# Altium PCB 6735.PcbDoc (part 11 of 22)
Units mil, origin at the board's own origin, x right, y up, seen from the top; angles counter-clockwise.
Board outline 2641.73 x 5165.35 mil, 6 copper layers (Top, Inner Layer 2, Inner Layer 3, Inner Layer 4, Inner Layer 5, Bottom), stack 35.7 mil thick; 1011 components, 790 nets, 4118 pads, 9325 vias.
Unrouted connection lines stored in the file: 4610.
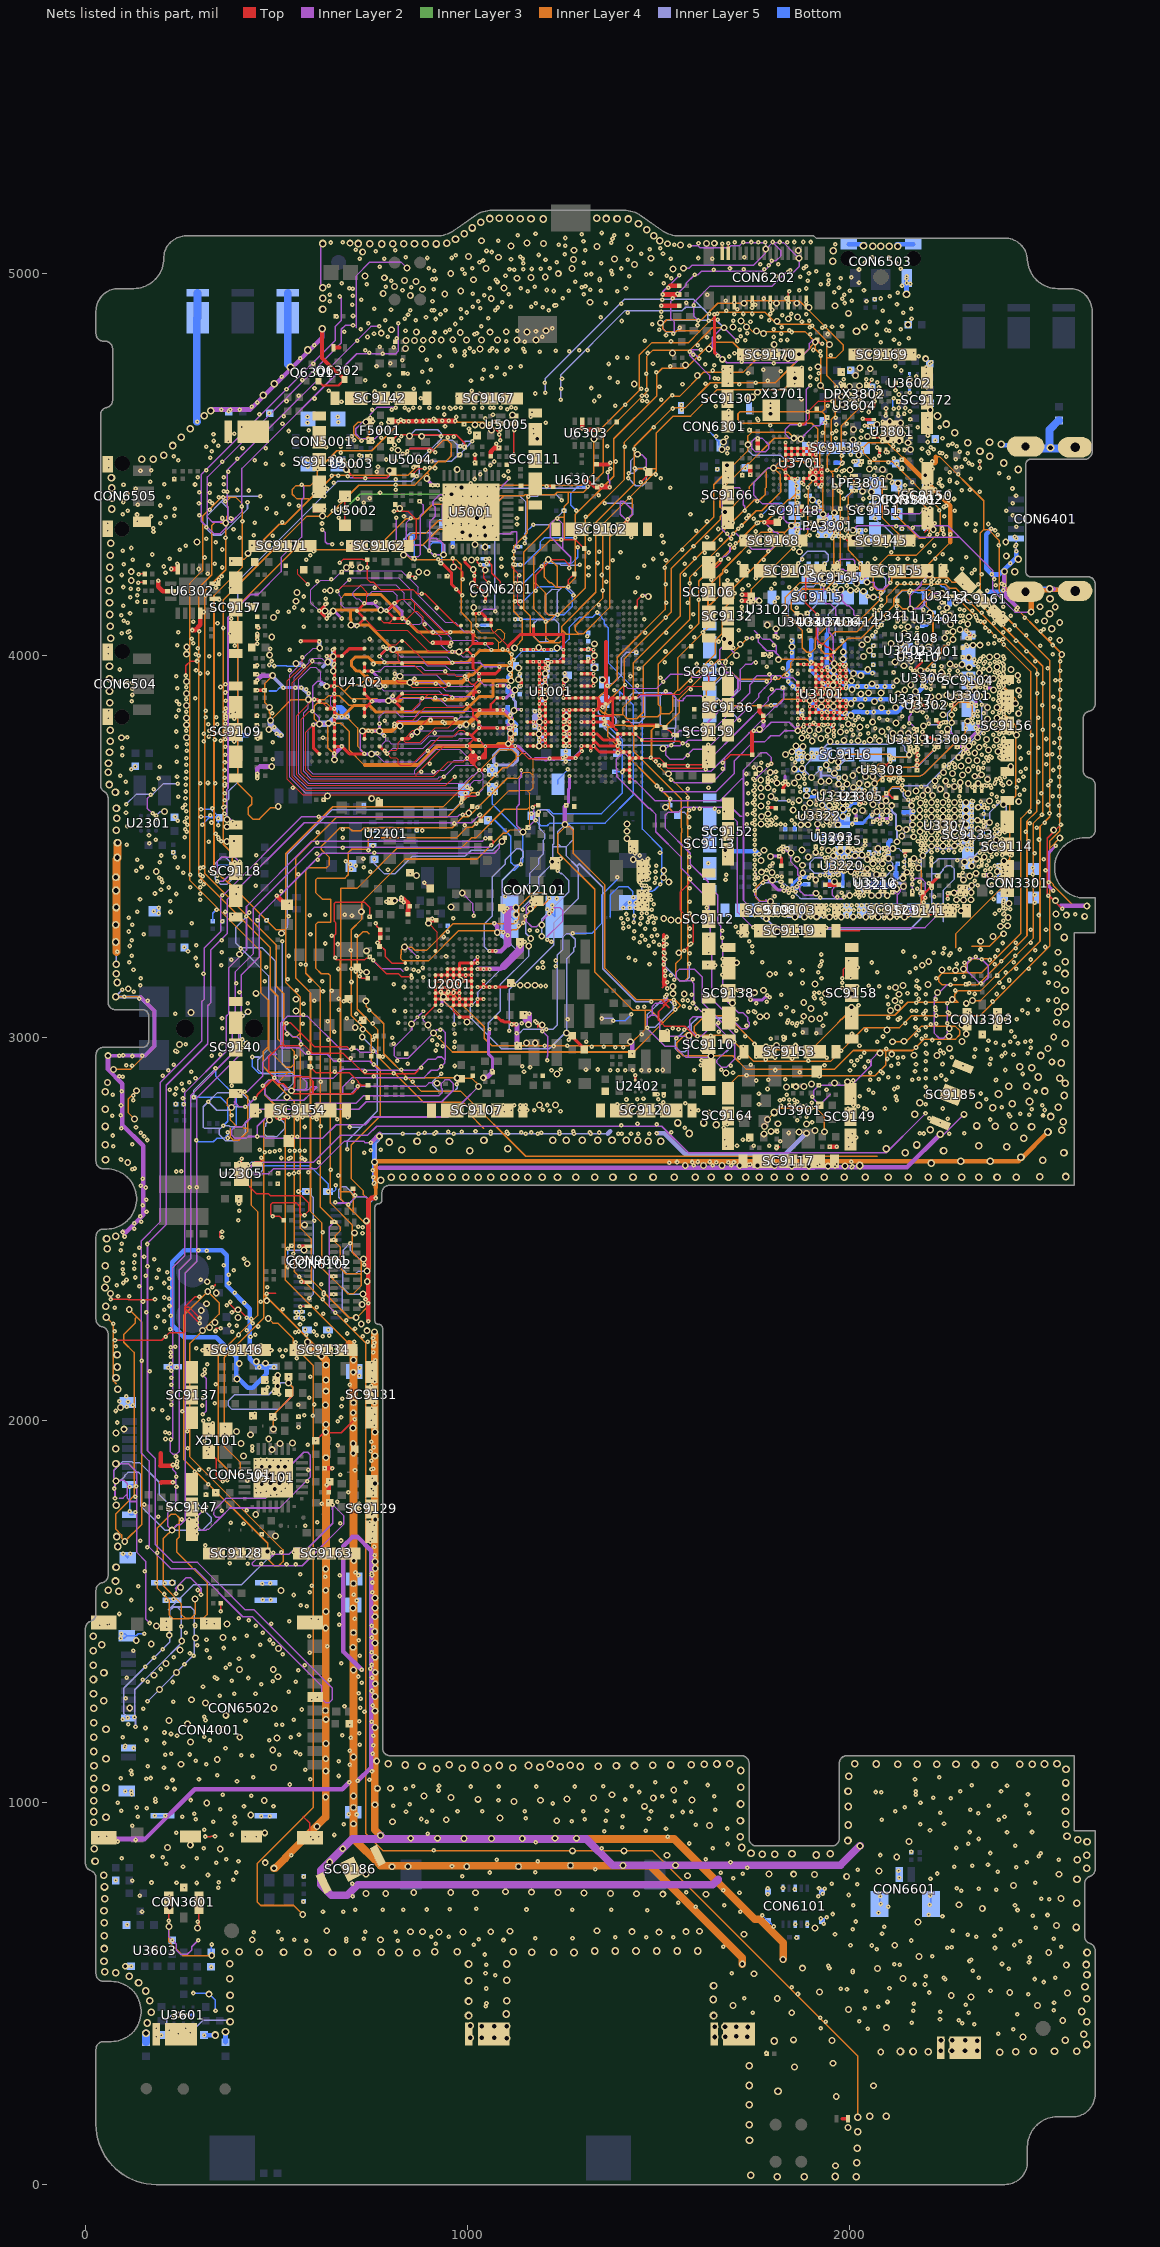
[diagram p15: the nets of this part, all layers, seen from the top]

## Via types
v1: diameter 12, hole 4, Top to Inner Layer 2, 3329 vias
v2: diameter 12, hole 4, Inner Layer 5 to Bottom, 3071 vias
v3: diameter 18, hole 10, Inner Layer 2 to Inner Layer 5, 1928 vias
v4: diameter 10, hole 4, Top to Inner Layer 2, 525 vias
v5: diameter 20, hole 12, Top to Bottom, 472 vias

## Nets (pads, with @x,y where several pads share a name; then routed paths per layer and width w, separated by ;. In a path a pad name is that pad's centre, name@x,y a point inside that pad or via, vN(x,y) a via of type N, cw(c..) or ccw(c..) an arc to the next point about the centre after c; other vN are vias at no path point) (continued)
D_GND: (continued)
  Bottom w8: U3601.6@231.43,443.38 256.33,443.38 U3601.9@256.43,443.38 260.91,443.38 U3601.2@281.43,443.38 ; v2(517.83,3916.61) v2(549.33,3916.61) v2(565.07,3916.61) ; C3248.2@1830.65,3545.59 v2(1830.65,3557.59) ; v2(1849.53,3391.68) 1849.53,3391.79 1848.24,3393.08 1848.24,3400.38 1868.13,3420.28 1880.65,3420.28 U3203.2@1886.76,3420.28 ; C3249.2@1855.65,3545.59 v2(1855.65,3559.59) ; v2@1858.65,3381.59 1858.65,3382.07 v2(1857.78,3382.95) 1856.03,3384.69 1864.29,3392.95 1872.88,3401.54 ; 1872.91,3401.57 U3203.1@1886.76,3401.57 ; U3203.14@1886.76,3630.9 1912.84,3630.9 1977.8,3565.94 U3203.50@1980.75,3565.94 ; U3203.40@1946.99,3401.57 1946.99,3454.43 1977.8,3485.24 U3203.49@1980.75,3485.24 ; v2(1974.87,3436.76) 1981.94,3429.69 1981.94,3415.72 1981.64,3415.42 U3203.38@1981.64,3401.57 ; v2(1981.65,3652.59) U3203.20@1981.64,3649.61 1981.64,3611.66 1980.75,3610.78 1980.75,3586.68 ; v2@1986.48,3436.4 1981.64,3439.52 1980.75,3440.4 1980.75,3473.59 U3203.49@1980.75,3483.15 ; U3203.34@2024.55,3437.6 2003.61,3437.6 1981.62,3459.59 1981.62,3483.15 U3203.49@1980.75,3483.15 ; U3203.31@2024.55,3489.57 2009.65,3489.57 1980.75,3489.57 U3203.49@1980.75,3485.24 ; U3203.24@2024.55,3613.58 2007.66,3613.58 1980.75,3586.68 ; C3243.2@2051.34,3580.59 2043.65,3572.9 2043.65,3572.55 2038.65,3567.55 2038.65,3566.59 2033.68,3561.61 U3203.27@2024.55,3561.61 1980.75,3561.61 U3203.50@1980.75,3565.94 ; L3234.2@2120.65,3430.59 2120.65,3450.59 C3289.2@2125.65,3455.59 ; U3602.6@2156.3,4688.09 v2@2156.3,4702.09 ; v2(2156.3,4704.09) U3602.9@2156.3,4713.09 2156.3,4725.09 ; L3415.2@2189.15,4078.59 2200.52,4078.59 v2(2208.16,4086.23) ; U3203.49@1980.75,3483.15 U3203.49@1980.75,3485.24 ; U3203.50@1980.75,3565.94 1980.75,3586.68
  Bottom w10: NTC6302.2@1860.65,3700.59 1871.65,3700.59 1881.15,3691.09 v2(1880.65,3690.59) ; L3414.1@1979.15,4038.59 1985.84,4031.91 v2(1985.84,3972.92) ; 2002.25,3956.09 v2@2061.65,3956.09 ; v2(2027.65,3380.59) 2027.3,3380.94 2046.95,3400.59 U3216.2@2070.65,3400.59 ; v2(2258.65,4149.88) 2260.25,4149.88 2260.25,4135.24 L3442.1@2260.57,4135.24
  Bottom w12: v2(310.3,391.09) v5(339.3,391.09) ; R3601.2@366.3,372.09 v5(366.3,400.09) ; v2(388.44,3791.68) 424.31,3791.68 ; v2(500.12,3796.33) 505.88,3796.33 505.88,3792.2 v2(511.65,3792.2) ; v2(655.06,3840) 655.06,3865.49 662.04,3865.49 ; v2(670.06,3840) 670.06,3857.47 662.04,3865.49 ; v2(685.06,3840) 685.06,3849.24 668.81,3865.49 662.04,3865.49 ; v2(698.52,786.81) v2@698.52,787.09 ; v2(755.68,2621.09) 755.68,2730.96 770.81,2746.09 ; C2402.2@756.31,3466.57 C2402.2@756.31,3467.09 ; v2(961.08,4285.11) 961.45,4284.74 C5013.2@961.45,4307.99 ; C10077.2@1104.95,3827.49 1118.95,3827.49 1127.45,3818.99 v2(1123.95,3815.49) ; C10072.2@1104.95,3865.49 1104.95,3851.78 v2(1111.93,3844.8) ; C10076.2@1105.95,3935.49 1105.95,3944.99 v2(1110.95,3949.99) ; v2(1107.95,3919.49) 1104.95,3916.49 C10073.2@1104.95,3905.49 1114.95,3895.49 v2(1117.95,3895.49) ; 1113.95,3765.49 1113.95,3777.49 1116.95,3780.49 1115.95,3781.49 v2(1115.7,3781.26) ; 1676.27,3488.59 1754.29,3488.59 v2(1762.23,3480.65) ; L3421.2@1849.15,4038.59 1849.15,3990.84 1838.65,3980.34 v2(1838.65,3932.59) v2(1850.65,3920.59) 1851.84,3921.78 1860.95,3912.67 v2(1862.13,3913.86) 1863.69,3915.41 1874.29,3904.8 1874.29,3904.32 1925.23,3853.38 1967.43,3853.38 1972.22,3848.59 v2(1986.65,3848.59) 2006.17,3848.59 2010.5,3852.92 2029.8,3852.92 2031.14,3851.59 v2(2045.65,3851.59) 2045.65,3852.13 2062.75,3852.13 v2(2062.75,3852.67) 2081.59,3852.67 2081.84,3852.42 v2(2100.84,3852.42) 2122.34,3852.42 v2(2140.34,3870.42) 2141.12,3869.64 2153.36,3881.88 v2(2154.15,3881.09) 2189.34,3916.27 v2(2189.34,3920.42) 2189.34,3923.77 2219.15,3953.59 ; L3411.1@1899.15,4038.59 1899.15,3961.92 1943.93,3917.14 v2(1974.68,3886.39) v2(2013.18,3886.39) v2(2039.68,3886.39) v2(2080.18,3886.39) v2(2108.18,3886.39) ; v2@1914.31,4402.09 v2(1919.31,4402.09) ; 1939.27,4056.21 1939.27,4053.35 1939.15,4053.24 1939.15,3971.11 v2(1940.34,3969.92) v2(1990.84,3919.42) v2(2019.84,3919.42) v2(2043.34,3919.42) v2(2071.34,3919.42) v2(2091.84,3919.42) v2@2112.56,3919.42 ; L3822.2@1963.31,4505.09 v2(1981.31,4505.09) ; v5(2035.58,5072.42) 2035.27,5076.21 v5@2038.7,5076.49 ; U3216.2@2070.65,3400.59 L3223.2@2115.65,3400.59 ; L3214.2@2100.65,3480.59 v2(2100.65,3485.59) 2100.65,3510.59 C3245.2@2105.65,3515.59 ; v2(2120.64,3405.02) 2120.36,3405.3 L3223.2@2115.65,3400.59 ; L3234.2@2120.65,3430.59 2120.65,3418.59 2115.65,3413.59 L3223.2@2115.65,3400.59 ; v5(2124.97,5071.19) 2123.08,5076.11 v5@2122.46,5076.49 ; C3255.2@2140.65,3590.59 2165.65,3590.59 v2(2165.65,3592.59) ; v5(2148.08,4946.11) v5@2148.23,4946.26 ; v2(2359.84,4169.49) 2361.81,4167.53 CON6401.7@2459.56,4167.53 2459.56,4175.08 v5(2523.05,4175.08) 2523.05,4172.29 2589.48,4172.29 CON6401.8@2589.48,4169.5 ; v2(2370.31,4332.09) 2356.3,4318.07 2356.3,4227.73 2371.54,4212.49 2391.06,4212.49 2435.31,4256.75 v2(2435.31,4273.09) ; v5(2396.3,4553.09) 2396.3,4550.27 2459.56,4550.27 CON6401.6@2459.56,4547.45 ; CON6501.16@451.32,2139.17 430.31,2160.18 430.31,2291.11 369.31,2352.11 369.31,2431.26 356.49,2444.09 258.29,2444.09 226.77,2412.57 226.77,2248.41 258.09,2217.09 342.31,2217.09 394.31,2165.09 394.31,2115.49 424.72,2085.09 437.18,2085.09 473.57,2121.48 CON6501.16@473.57,2139.18 ; CON6501.16@451.32,2139.17 454.31,2139.17 CON6501.16@455.39,2139.17 ; CON6501.16@451.32,2139.17 CON6501.16@455.39,2139.17 ; CON6501.16@455.39,2139.17 CON6501.16@473.57,2139.18 ; CON6501.16@455.39,2139.17 CON6501.16@473.57,2139.18 ; v5@2038.7,5076.49 2035.58,5076.49 CON6503.5@1996.66,5076.49 v5@2038.7,5076.49 ; v5@2122.46,5076.49 2124.97,5076.49 CON6503.4@2165.95,5076.49 v5@2122.46,5076.49 ; v5@2148.23,4946.26 2148.23,4975.09 CON6503.1@2148.23,4987.91 v5@2148.23,4946.26
  Bottom w20: L3603.2@158.3,372.09 v5(158.3,396.09) ; v2(292.3,4612.09) 292.08,4611.86 291.31,4612.63 291.31,4884.13 ANT5002.2@293.31,4884.13 ANT5002.1@293.31,4949.09 ; ANT5001.1@529.31,4949.09 ANT5001.2@529.31,4884.13 529.31,4762.09 v5(536.53,4754.87) ; R3622.2@2546.95,4615.49 2522.3,4590.84 v5@2522.3,4542.09 ; CON6401.9@2589.48,4545.48 2589.48,4542.09 v5@2522.3,4542.09 ; CON6401.6@2459.56,4547.45 2459.56,4542.09 v5@2522.3,4542.09 ; CON6401.6@2459.56,4547.45 2459.56,4553.27 CON6401.6@2459.56,4547.45
  other v1: 2387.65,394.26 2427.57,406.04 2325.38,419.04 2294.15,422.15 2161.63,423.05 1936.69,425.91 2024.72,426.72 2438.1,445.42 1745.4,449.11 2310.76,449.54 2236.6,451.65 2533.27,456.18 2073.88,465.13 1047.3,466.82 2167,473.15 2534.12,475.88 1723.47,487.07 2367.87,506.5 1992.39,510.8 1048.99,512.38 2103.66,513.97 1847.48,516.6 2169.69,523.34 2196.53,523.35 2483.98,537.66 2245.8,541.24 2537.81,540.97 1072.61,547.81 1691.41,552.87 2007.56,555.83 2321.91,559.15 1943.15,572.58 1048.15,574.81 2115.96,576.17 2398.02,577.06 2317.59,588.31 2470.55,594.07 2215.35,596.76 2266.39,620.94 1668.63,622.05 2057.76,625.41 2429.79,626.69 2161.09,638.5 546.4,640.48 1093.7,639.77 1028.74,641.45 682.78,643.06 2533.66,642.76 1176.38,643.99 1274.24,644.83 1385.59,646.52 1467.43,646.52 1537.45,647.36 904.94,648.2 950.4,648.2 2378.32,651.38 2308.73,653.27 1961.05,654.96 504.37,661.07 731.68,661.93 811.45,661.93 2007.56,668.03 2485.77,671.98 2090.23,673.93 2242.22,702.42 2517.11,705.11 1955.68,707.79 147.98,714.25 2438.65,718.22 2100.74,726.6 2500.99,747.19 141.97,755.42 2291.01,768.42 2382.55,771.37 346.98,776.87 1952.1,787.48 2484.87,789.28 122.25,794.88 2210.88,800.02 320.54,809.85 1719.31,813.15 395.01,816.32 2435.63,830.46 2272.66,831.36 255.2,831.76 2361.31,836.73 211.45,839.48 341.83,842.05 400.32,846.11 94.51,853.97 175.5,859.41 2494.19,858.8 2432.74,886.53 2309.31,892.04 2337.07,904.14 313.95,910.49 651.05,914.62 237.56,920 2209.6,927.35 675.77,942.2 391.26,945.84 892.56,949.6 1361.01,951.68 2389.43,954.48 288.65,956.14 252.96,962.23 137.12,962.76 1535.5,963.35 1406.09,963.88 2469.26,970.97 838.62,974.93 1585.04,974.93 1037.66,976.25 973.49,976.78 1149.01,976.78 1302.36,976.78 1479.72,976.78 907.36,977.73 2314.63,981.01 352.98,981.87 160.69,984.52 2143.38,986.92 414.74,989.59 491.94,989.59 805.2,991.06 1222.73,996.98 84.32,999.12 2184.72,998.73 1080.59,1005.86 1412.46,1007.37 183.05,1008.69 1509.51,1015.85 121.29,1020.62 2465.94,1020.93 1448.52,1026.99 2067.24,1026.97 2171.95,1028.98 2288.74,1028.98 2395.47,1028.98 923.65,1031.03 837.78,1035.48 213.27,1038.3 743.1,1058.69 170.3,1063.61 121.34,1073.02 749.61,1081.27 162.56,1094.18 691.95,1098.49 288.09,1108.31 407.65,1123.15 506.8,1124.26 751.9,1126.8 224.95,1127.6 550.25,1130.95 691.95,1135.49 366.43,1140.97 104.63,1147.66 717.69,1150.43 752.86,1149.76 160.33,1162.14 325.21,1162.14 481.18,1162.14 693.95,1169.49 536.88,1169.94 752.85,1174.67 223.83,1178.85 716.83,1180.88 156.99,1194.45 499,1203.36 112.43,1204.47 749.42,1210.98 716.54,1211.91 418.79,1213.38 314.07,1214.5 544.68,1215.61 151.42,1244.58 718.98,1247.53 751.33,1253.45 229.4,1263.52 719.95,1270.49 105.75,1272.43 715.25,1285.44 749.6,1291.26 459.78,1309.03 722.95,1312.49 228.29,1314.76 490.34,1316.63 383.07,1318.19 150.31,1320.33 425.82,1325.18 107.97,1325.9 749.6,1326.25 338.76,1327.52 714.1,1329.11 556.98,1345.55 367.52,1352.39 749.13,1359.81 401.72,1375.71 325.54,1378.04 438.26,1381.93 717.1,1383.44 516.69,1387.39 273.46,1389.7 749.13,1392.43 124.68,1396.09 361.3,1403.69 292.12,1411.47 491.81,1414.45 714.63,1424.06 481.76,1424.78 389.28,1428.57 748.66,1431.19 262.58,1443.34 463.48,1443.47 445.2,1462.17 286.68,1464.33 663.84,1464.42 211.45,1473.99 427.46,1476.49 704.97,1480.53 664.48,1491.5 171.45,1505.83 578.73,1512.77 665.13,1539.85 545.21,1542.43 701.5,1543.44 587.07,1549.38 750.13,1550.16 592.03,1566.72 750.53,1575.24 627.2,1590 665.13,1594.66 749.54,1599.34 706.45,1602.39 155.12,1604.81 526.04,1622.69 549.72,1622.88 424.15,1623.7 460.02,1624.42 377.99,1625.61 441.76,1644.22 653.61,1644.46 394.59,1647.53 675.48,1646.89 756.44,1646.66 430.68,1650.2 381.28,1650.8 408.82,1650.8 695.89,1652.48 452.11,1654.04 512.33,1653.84 545.14,1653.84 564.14,1658.59 755.08,1668.27 745.46,1682.37 291.35,1702.37 752.04,1707.34 290.76,1718.53 755.08,1725.02 743.76,1732.42 291.06,1732.91 251.44,1740.04 291.28,1747.59 749.09,1753.07 236.51,1766.89 291.78,1767.74 291.35,1781.5 747.62,1783.3 752.4,1803.35 458.8,1809.55 446.26,1809.75 472.49,1813.41 748.35,1820.18 75.66,1820.99 445.85,1822.08 238.1,1826.01 445.53,1836.92 749.83,1848.2 237.34,1851.77 445.22,1851.75 445.17,1866.92 297.9,1869.63 747.79,1871.1 239.73,1876.18 239.62,1892.16 510.62,1894.35 530.99,1893.83 747.79,1893.63 491.79,1895 459.03,1895.9 474.51,1895.64 236.84,1904.89 746.86,1918.26 748.05,1943.14 223.06,1949.29 209.43,1950.62 219.44,1966.07 83.34,1993.67 308.05,1997.81 748.22,1999.43 322.41,2002.64 215.98,2005.61 668.67,2007.86 572.8,2013.26 443.09,2017.15 78.85,2023.96 749.41,2031.17 107.61,2035.25 669.92,2036.04 306,2038.17 224.57,2040.13 598.47,2040.98 88.2,2049.02 224.61,2054.57 306.92,2057.68 749.01,2060.54 107.26,2062.37 688.57,2062.98 224.6,2073.63 469.31,2075.09 476.53,2086.06 748.22,2090.31 224.59,2092.69 691.05,2092.82 224.25,2110.84 223.92,2128.99 749.81,2128.8 312.58,2132.46 318.96,2145.8 223.58,2147.14 749.41,2150.23 223.25,2165.29 410.62,2174.09 364.73,2175.61 388.23,2175.61 223.1,2178.07 677.66,2178.18 752.56,2178.07 456.19,2181.52 483.77,2181.52 601.65,2181.54 662.1,2181.58 523.97,2182.55 306.29,2182.95 376.58,2183.49 401.62,2183.13 508.52,2183.57 543.44,2182.77 562.31,2183.56 582.73,2182.77 620.43,2183.17 642.68,2182.89 222.61,2191.16 79.39,2192.88 753.66,2193.98 738.59,2205.21 752.37,2214.28 725.59,2218.96 621.34,2219.79 637.37,2221.37 400.43,2222.42 443.79,2223.06 578.12,2223.8 384.53,2231.53 76.39,2232.38 557.66,2231.92 597.73,2231.92 422.28,2235.29 221.57,2237.42 705.31,2239.5 396.13,2247.1 375.99,2248.78 561.37,2250.45 602.79,2251.32 72.31,2252.09 437.88,2253.85 682.17,2261.6 569.47,2264.39 223.48,2272.57 556.74,2276.37 219.79,2298.68 621.34,2316.02 732.74,2315.76 219.25,2317.15 623.12,2333.84 219.05,2346.41 475.31,2348.09 617.06,2355.94 98.37,2358.81 301.35,2367.07 219.59,2369.61 559.54,2375.45 375,2380 98.66,2382.57 387.5,2392.5 729.77,2406.15 555.91,2408.2 97.21,2411.26 414.88,2421.83 543.82,2435.41 91.99,2444.01 94.6,2461.1 724.81,2488.8 725.64,2505.13 127.55,2515.44 399.73,2523.32 143.1,2533.66 402.56,2547.66 150.02,2562.51 401.7,2566.21 144.36,2613.18 754.25,2618.81 753.28,2635.92 532.64,2643.24 545.62,2645.83 558.33,2648.95 582.5,2648.95 751.67,2653.34 129.05,2658.42 2004.64,2661.93 1738.86,2668.83 1784.08,2669.13 1870.63,2669.08 1820.01,2670.33 1920.71,2669.92 1965.94,2670.14 1527.76,2673.46 1696.75,2674.54 1547.8,2675.24 1587.47,2675.24 1602.34,2675.44 1633.88,2675.44 1650.54,2675.04 1682.2,2674.64 2003.3,2675.55 93.17,2681.05 511.89,2685.91 565.92,2685.91 536.95,2686.69 729.81,2699.15 469.31,2701.09 482.31,2702.09 495.31,2703.09 534.31,2705.09 547.31,2705.09 560.31,2705.09 573.31,2705.09 508.31,2706.09 746.81,2706.15 456.31,2707.09 772.81,2707.15 1997.43,2715.2 1676.29,2716.78 122.41,2722.02 2006.01,2727.21 1672.47,2733.02 1720.31,2733.56 1735.31,2733.56 372.31,2738.15 1995.4,2739.07 2017.15,2739.52 540.03,2741.35 553.93,2741.54 830.35,2749.06 871.41,2749.07 912.25,2749 963.78,2749.09 1060.48,2749.01 1105.43,2749.08 1151.63,2749.07 1183.14,2749.09 1240.36,2749.06 1278.21,2749.04 1321.62,2749.08 1394.49,2749.08 1427.39,2749.08 1475.58,2749.04 2006.01,2749.81 2192.95,2749.83 371.81,2753.15 1809.69,2754.87 93.56,2763.73 1669.78,2764.98 1900.93,2779.85 2418.91,2794.79 91.84,2798.02 382.31,2798.15 1631.54,2801.32 2446.16,2802.06 444.67,2802.99 1408.06,2803.97 1426.44,2804.08 1445.17,2803.74 1072.22,2806.52 1095.81,2807.08 1037.69,2808.4 1051.4,2808.51 1242.86,2808.5 456.34,2808.64 1023.46,2809.58 2008.21,2808.79 1136.63,2810.3 1174.6,2810.3 1214.71,2809.94 1555.67,2810.13 1584.22,2810.3 1602.8,2810.47 1113.93,2810.9 1155.64,2811.28 1196.02,2811.66 2043.39,2813.2 2475.69,2812.96 1994.99,2815 2091.21,2815.31 1900.31,2816.56 2397.56,2818.87 1502.52,2821.63 92.98,2823.44 1820.97,2823.02 2009.41,2824.39 2502.94,2824.32 1841.31,2825.56 2198.77,2826.59 1900.31,2830.56 1511.83,2832.12 1854.31,2837.56 1841.31,2838.56 1415.49,2838.83 1443.9,2839.24 1498.89,2839.26 1827.01,2839.31 1459.96,2840.48 2357.23,2839.81 2010.61,2841.58 2119.56,2846.63 1513.35,2848.53 2198.68,2849.03 1834.94,2851.02 1497.25,2852.32 2342.38,2854.66 416.21,2859.07 2486.59,2859.74 95.15,2860.65 2048.89,2863.98 2125.66,2870.4 2198.6,2871.47 971.85,2878.34 1264.15,2886.09 2381.98,2889.3 2053.77,2890.54 2162.72,2890.21 2075.13,2891.9 2198.51,2893.92 2100.37,2897.43 97.67,2898.88 202.17,2901.17 2238.58,2901.74 2452.52,2905.62 1694.23,2908.71 2080.68,2913.15 2170.47,2912.82 2000.31,2915.56 216.63,2915.63 1663.22,2916.33 2198.42,2916.36 2406.72,2916.03 2039.44,2923.99 121.84,2927.38 2107.71,2927.45 2011.25,2928.71 231.34,2930.17 2173,2931.58 2126.81,2932.12 2241.38,2931.6 2198.33,2938.81 2019.56,2941.96 2368.32,2945.61 2124.78,2948.63 122.32,2952.58 88.1,2952.95 148.43,2953.68 2428.06,2955.87 2245.11,2960.54 2406.59,2960.54 582.4,2960.79 2037.33,2961.19 2198.24,2961.25 239.6,2963.84 2359.92,2968.5 2095.44,2971.25 2328.18,2970.81 2173.03,2974.9 2472.96,2974.66 262.76,2983.71 2198.15,2983.69 2233.71,2986.54 2381.26,2987.86 2071.25,2990.36 2419.65,2990.41 2458.43,2990.1 2431.79,3002.54 2198.06,3006.14 2173.58,3007.51 527.31,3010.28 2348.22,3009.6 1566.74,3021.09 1551.63,3022.5 1205.95,3022.83 1536.87,3025.08 2171.74,3028.36 2198.14,3027.87 2384.51,3028.19 2307.79,3031.46 2226.12,3037.42 1849.54,3038.29 1862.49,3038.53 2254.49,3038.49 1836.11,3039.42 1874.57,3041.21 2381.56,3049.44 2436.46,3049.21 2171.74,3049.88 2198.21,3049.6 2307.2,3050.32 2131.35,3053.15 2225.56,3058.64 2414.31,3059.01 2256.64,3066.79 1733.95,3068.3 1747.95,3069.3 2306.61,3069.19 2383.92,3068.91 2173.93,3071.04 2198.29,3071 2450.46,3072.54 1542.72,3074.33 1598.55,3076.9 1580.74,3078.73 2223.49,3080.66 1565.73,3082.59 1541.65,3087.84 2099.89,3088.39 2173.47,3092.26 2198.36,3092.4 2134.31,3094.09 675.95,3095.83 2373.25,3095.77 162.97,3097.52 1562.82,3098.42 1575.79,3097.91 1539.01,3099.97 2224.53,3101.52 1925.34,3102.26 1908.31,3103.56 101.46,3107.28 2098.31,3108.09 1585.99,3113.17 2173.41,3114.27 2198.44,3113.81 2326.26,3114.94 2384.63,3114.92 1906.31,3118.56 1919.31,3118.56 2312,3118.32 126.82,3120.66 2275.63,3124.12 1979.72,3130.76 2103.31,3131.09 2401.19,3132.51 2173.59,3134.67 1190.95,3135.83 1203.95,3135.83 142.97,3137.72 1979.56,3143.83 2417.22,3149.47 1540.24,3151.85 2276.2,3153.78 144.58,3156.17 2226.19,3156.37 2297.81,3160.23 1531.62,3163.63 1806.08,3168.58 2408.31,3171.09 2156.8,3171.77 706.95,3173.83 125.67,3178.77 2259.97,3182.66 1921.31,3187.56 1628.05,3190.84 2279.31,3193.41 2378.49,3192.79 2299.87,3196.8 2428.31,3198.09 2396.31,3200.09 1926,3200.83 2365.83,3203.84 381.3,3204.99 2313.15,3207.47 2328.89,3212.1 2379.97,3213.04 120.6,3215.2 2432.73,3214.86 1925.08,3218.28 2243.57,3221.7 2263.69,3221.79 1630.31,3223.09 1745,3224.23 406.71,3233.88 2434.4,3234.07 1744.95,3240.3 2434.4,3248.62 1148.95,3251.83 1737.12,3253.04 121.52,3255.78 1666.59,3262.43 1666.32,3280.48 1846.31,3281.56 1830.65,3285.59 1861.31,3288.56 122.9,3295.91 2401.78,3306.44 962.31,3313.09 1452.33,3313.25 1491.93,3313.37 1474.63,3313.77 1799.65,3321.59 1812.65,3321.59 1927.65,3321.59 2023.65,3320.59 2089.65,3321.59 2124.65,3321.59 1751.29,3321.6 1895.65,3322.59 1960.65,3322.59 1991.65,3322.59 2055.65,3322.59 2243.65,3322.59 2256.65,3322.59 2269.65,3322.59 2589.39,3323.71 2403.59,3325.93 1738.65,3329.59 2188.14,3329.37 135.82,3330.03 2134.64,3329.74 2149.95,3330.68 2169.56,3333.54 1727.65,3335.59 1795.65,3334.59 1815.65,3334.59 1840.65,3334.59 1853.65,3334.59 1866.65,3334.59 1879.67,3334.8 1892.65,3334.59 1905.65,3334.59 1918.65,3334.59 1931.65,3334.59 1944.65,3334.59 1958.65,3334.59 1971.65,3334.59 1984.65,3334.59 1997.65,3334.59 2010.65,3334.59 2023.65,3334.59 2036.65,3334.59 2049.65,3334.59 2062.65,3334.59 2075.65,3334.59 2088.65,3334.59 2101.65,3334.59 2114.65,3334.59 2235.65,3334.59 2248.65,3334.59 2261.65,3334.59 2274.65,3334.59 2419.65,3336.65 2198.26,3338.06 2407.65,3337.75 2186.66,3342.17 1470.31,3342.91 1451.19,3343.75 1806.65,3344.59 2269.65,3345.59 2282.65,3345.59 1848.64,3346.42 1860.65,3346.59 1873.65,3346.59 1886.65,3346.59 1899.65,3346.59 1912.65,3346.59 1925.65,3346.59 1938.65,3346.59 1951.65,3346.59 1965.65,3346.59 1978.65,3346.59 1991.65,3346.59 2004.65,3346.59 2017.65,3346.59 2030.65,3346.59 2043.65,3346.59 2056.65,3346.59 2069.65,3346.59 2082.65,3346.59 2095.65,3346.59 2108.65,3346.59 2230.65,3346.59 2243.65,3346.59 2256.65,3346.59 2401.65,3348.72 1179.28,3351.99 300.51,3361.57 2402.65,3360.72 142.73,3363.24 1170.95,3369.24 1850.65,3369.59 1477.35,3373.26 2287.65,3375.59 2302.65,3375.59 300.17,3377.34 1839.76,3379.72 2411.15,3380.53 2020.65,3380.59 511.95,3383.83 2045.97,3383.94 1827.65,3384.59 1849.65,3386.59 1476.05,3391.92 2402.65,3393.59 300.51,3394.3 2287.65,3395.59 2302.65,3395.59 1823.65,3396.59 1461.87,3398.61 1750.65,3401.59 1504.02,3402.34 1489.54,3405.86 200.52,3406.76 1449.63,3406.77 1821.65,3408.59 300.68,3409.9 1460.06,3414.2 1674.61,3414.31 1474.11,3416.27 1491.97,3418.39 2393.46,3418.45 193.39,3419.05 2380.9,3419.43 2023.23,3420.66 2011.11,3423.04 2227.87,3423.87 300.85,3427.19 1676.21,3427.16 1750.65,3427.59 1971.38,3427.29 2033.62,3426.75 557.26,3428.11 2400.65,3428.59 1475.1,3431.72 2019.65,3432.59 1491.34,3434.36 1983.82,3434.87 2411.15,3435.65 2030.65,3438.59 2353.65,3438.59 2060.66,3440.27 2085.78,3440.35 1750.65,3440.59 2366.65,3441.59 2400.65,3441.59 300,3444.49 1975.87,3443.93 1963.65,3444.59 2073.65,3445.59 1987.62,3446.5 384.87,3447.46 2020.65,3446.59 2141.65,3446.59 1474.16,3449.01 1939.65,3448.59 1952.65,3449.59 1493.07,3450.21 2009.65,3451.59 2032.65,3450.59 2357.65,3451.59 2378.65,3450.59 2390.65,3450.59 1750.65,3453.59 1997.65,3453.59 1972.65,3455.59 1629.9,3457.05 2156.16,3458.15 2212.86,3458.15 2345.14,3458.15 1984.65,3458.59 194.78,3459.81 1937.65,3460.59 2141.65,3460.59 1456.87,3462.97 1949.65,3462.59 1962.65,3462.59 2363.65,3463.59 2073.65,3465.59 1750.65,3466.59 1471.69,3468.14 1971.65,3471.59 1984.65,3471.59 2213.65,3471.59 1941.65,3472.59 2371.65,3473.59 1674.25,3474.17 198.02,3477.19 1449.8,3477.18 2423.31,3478.09 1750.65,3479.59 2398.65,3478.59 2383.65,3480.59 1437.73,3482.93 2091.65,3482.59 2213.65,3485.59 2243.65,3485.59 2272.65,3485.59 1825.65,3486.59 2352.03,3489.45 1959.65,3491.59 2184.81,3491.46 2198.65,3490.59 2228.65,3490.59 2258.65,3490.59 2288.65,3490.59 2318.65,3490.59 2390.65,3491.59 1750.65,3492.59 1813.65,3492.59 2019.65,3492.59 2306.65,3492.59 2031.65,3494.59 2402.65,3494.59 2007.65,3496.59 2379.65,3498.59 2039.65,3503.59 2198.65,3503.59 2228.65,3503.59 2258.65,3503.59 2288.65,3503.59 2318.65,3503.59 2185.95,3504.37 1750.65,3505.59 2306.65,3505.59 2390.65,3504.59 2402.65,3507.59 2352.03,3508.35 167.39,3509 2040.65,3515.59 2179.65,3514.59 2198.65,3516.59 2228.65,3516.59 2258.65,3516.59 2288.65,3516.59 2318.65,3516.59 183.98,3518.51 1750.65,3518.59 2398.65,3520.59 259.34,3525.43 347.47,3524.76 2186.65,3524.59 1975.65,3526.91 2352.03,3527.24 2198.65,3529.59 2228.65,3529.59 2258.65,3529.59 2288.65,3529.59 2318.65,3529.59 166.21,3529.91 1750.65,3531.59 2378.65,3533.59 2390.65,3532.59 264.93,3539.93 2198.65,3542.59 2228.65,3542.59 2258.65,3542.59 2288.65,3542.59 2318.65,3542.59 1750.65,3544.59 2390.65,3545.59 2352.03,3546.14 2378.65,3546.59 1784.65,3555.59 2198.65,3555.59 2228.65,3555.59 2258.65,3555.59 2288.65,3555.59 2318.65,3555.59 266.85,3557.58 1750.65,3557.59 2385.12,3557.47 2006.65,3559.59 2078.65,3560.59 2097.65,3564.59 385.52,3566.04 1796.65,3567.59 1784.65,3569.59 2198.65,3568.59 2228.65,3568.59 2258.65,3568.59 2288.65,3568.59 2318.65,3568.59 1750.65,3570.59 2071.65,3570.59 2085.65,3570.59 186.94,3573.45 1896.65,3572.59 1960.65,3575.59 265.54,3575.63 1805.65,3576.59 1948.65,3580.59 2198.65,3581.59 2228.65,3581.59 2258.65,3581.59 2288.65,3581.59 2318.65,3581.59 2547.05,3582.27 1750.65,3583.59 363.8,3586.56 1961.65,3587.59 1656.85,3591.99 1671.07,3592.38 263.92,3593.52 1950.65,3592.59 2198.65,3594.59 2228.65,3594.59 2258.65,3594.59 2288.65,3594.59 2318.65,3594.59 1750.65,3596.59 1591.52,3599.88 1607.52,3599.88 1960.65,3600.59 2352.03,3602.83 363.9,3604.32 2198.65,3607.59 2228.65,3607.59 2258.65,3607.59 2288.65,3607.59 2318.65,3607.59 2547.28,3607.52 1750.65,3609.59 261.34,3610.05 2025.22,3610.53 1961.65,3613.59 2036.13,3615.91 2198.65,3620.59 2228.65,3620.59 2258.65,3620.59 2288.65,3620.59 2318.65,3620.59 364,3622.07 1750.65,3622.59 765.55,3624.58 261.74,3627.4 2019.26,3630.94 2384.65,3630.59 2286.65,3632.59 2547.51,3632.77 1750.65,3635.59 2444.15,3636.09 2371.65,3637.59 364.64,3640.57 262.14,3644.76 2399.65,3645.59 2022.98,3647.32 2038.33,3647.32 1750.65,3648.59 2137.38,3648.61 178.61,3650.58 1008.76,3651.33 1506.99,3651.06 2326.24,3653.03 2345.14,3653.03 542.95,3654.83 2369.65,3654.59 2436.65,3656.09 2547.74,3658.02 2357.65,3659.59 364.26,3660.5 1750.65,3661.59 2136.65,3661.59 2401.65,3661.59 262.55,3662.11 2378.65,3664.59 2125.65,3668.59 2441.65,3673.59 2085.65,3675 2394.65,3674.59 2382.65,3676.59 192.29,3679.33 262.95,3679.46 448.95,3678.83 2114.65,3679.59 364.51,3680.68 2127.65,3680.59 2405.65,3681.59 239.59,3683.35 2547.97,3683.27 2086.65,3687.59 878.78,3695.91 2446.65,3696.09 263.35,3696.82 910.56,3696.81 2059.65,3699.59 364.76,3700.87 2072.65,3700.59 2335.95,3703.57 1666.93,3704.25 2548.2,3708.52 194.69,3709.66 263.76,3714.17 2247,3714.64 2273.73,3715.33 2259.63,3716.23 900.27,3717.33 365.01,3721.05 238.97,3722.77 1492.31,3724.09 2361.65,3725.59 489.95,3729.49 2115.04,3731.22 2446.65,3731.09 264.16,3731.93 1479.31,3733.09 2416.65,3733.59 2548.43,3733.77 2390.65,3734.59 2366.65,3736.59 2103.6,3738.43 2178.65,3739.59 365.26,3741.23 2168.66,3748.15 2308.12,3748.95 264.56,3750.9 2220.65,3754.59 2402.65,3754.59 2297.21,3757.68 2548.66,3759.02 365.51,3761.41 2444.15,3761.09 238.36,3762.19 2390.65,3764.59 2154.65,3767.59 2220.65,3766.59 2416.65,3766.59 265.17,3768.46 2295.65,3769.59 2402.65,3769.59 2324.4,3772.55 489.95,3773.49 2129.65,3780.59 2142.65,3780.59 2155.65,3780.59 2255.65,3780.59 2268.65,3781.59 365.75,3781.59 2295.65,3782.59 2548.89,3784.27 2402.65,3784.59 109.4,3787.11 2390.65,3794.59 2416.65,3796.59 2402.65,3798.59 2334.61,3800.57 237.74,3801.61 366,3801.78 263.7,3803.51 2444.15,3806.09 2549.12,3809.52 2329.79,3811.56 2402.65,3811.59 493.47,3813.31 448.95,3817.83 366.25,3821.96 2238.65,3822.59 2390.65,3822.59 2321.64,3824.02 2402.65,3824.59 2416.65,3824.59 934.29,3826.72 2441.65,3828.59 902.71,3831.66 2549.35,3834.77 2320.91,3836 2402.65,3839.59 237.13,3841.03 2334.65,3841.59 366.5,3842.14 488.95,3849.49 2323.65,3848.59 2390.65,3850.59 2402.65,3853.59 2416.65,3852.59 263.92,3853.81 2549.58,3860.02 366.75,3862.32 2446.65,3863.59 2402.65,3866.59 2167.65,3871.59 2319.27,3876 2390.65,3878.59 2402.65,3879.59 1656.54,3880.2 238.97,3881.07 2416.65,3880.59 367,3882.51 2310.65,3885.59 2549.81,3885.27 263.82,3886.1 881.56,3888.61 915.1,3889.6 2390.65,3891.59 2416.65,3893.59 2444.15,3893.59 2288.12,3894.98 2402.65,3894.59 584.36,3901.26 366,3903.37 2310.65,3903.59 2390.65,3904.59 2402.65,3908.59 2550.04,3910.52 577.95,3912.49 240.21,3914.94 263.7,3917.12 2199.65,3916.59 2340.65,3917.59 2390.65,3917.59 2402.65,3921.59 366.41,3925.04 866.37,3926.21 2194.65,3927.59 2348.65,3926.59 2416.65,3927.59 2336.65,3929.59 2390.65,3930.59 2441.65,3933.59 2402.65,3934.59 2550.27,3935.77 2207.65,3938.59 2195.65,3940.59 2249.65,3941.59 2265.65,3940.59 2390.65,3943.59 237.13,3945.74 2277.65,3946.59 2402.65,3949.59 2258.65,3950.59 2290.65,3950.59 2378.65,3956.59 2390.65,3956.59 2170.06,3960.28 534.95,3961.49 2550.5,3961.02 1634.31,3963.09 1655.31,3963.09 2402.65,3963.59 2159.65,3967.59 2402.65,3976.59 2366.65,3978.59 1637.31,3982.09 2354.65,3984.59 2378.65,3984.59 2390.65,3984.59 2550.15,3985.24 486.95,3986.09 1675.31,3986.09 2339.15,3986.09 2325.65,3990.59 2403.65,3991.59 2349.65,3998.59 288.36,4003.4 1793.7,4003.23 1778.09,4004.29 2232.28,4008.34 534.95,4015.49 294.09,4019.17 2176.65,4019.59 1695.31,4021.09 2188.65,4024.59 2306.65,4024.59 2530.28,4027.94 2402.2,4029.33 2362.17,4031.26 2378.01,4032.93 2175.65,4034.27 2390.65,4040.59 2523.76,4044.04 117.65,4047.55 2379.15,4051.09 2175.65,4056.91 909.38,4061.43 2067.65,4062.59 114.82,4063.91 2365.03,4064.17 1709.15,4066.09 1892.65,4067.23 2506.78,4069.28 2353.69,4073.08 2175.81,4073.65 570.95,4075.49 2072.65,4074.59 2118.31,4075.15 2133.81,4075.65 2083.81,4081.15 887.87,4082.56 110.73,4085.93 2068.65,4087.59 2191.77,4088.22 2288.81,4087.65 2341.86,4089.41 2169.16,4090.45 2488.51,4090.17 2126.93,4092.32 2330.36,4099.91 1716.65,4101.09 93.42,4105.44 2288.31,4104.65 2063.65,4107.59 1889.11,4111.67 2242.18,4112.78 503.24,4114.62 532.09,4115.44 1716.65,4116.09 568.95,4119.49 2076.65,4119.59 2063.65,4120.59 2287.81,4121.15 1860.78,4125.33 2234.15,4125.44 546.31,4126.09 1716.65,4128.59 2122.77,4129.43 2082.81,4130.65 2240.43,4139.16 135.95,4140.83 2081.31,4146.15 1858.8,4148.78 2228.06,4154.47 570.95,4154.83 2282.3,4155.05 135.95,4157.83 2081.31,4164.15 1135.31,4169.09 1957.06,4170.5 2158.31,4170.65 1719.15,4173.59 1944.15,4173.59 2020.93,4173.28 137.95,4173.83 970.42,4174.31 1859.13,4175.45 1959.65,4182.59 1991.65,4183.59 2403.65,4184.59 2142.81,4189.15 1135.31,4190.09 2124.31,4189.65 2158.81,4189.65 2175.81,4189.65 2105.81,4190.65 605.95,4194.49 2252.81,4195.15 2195.81,4195.65 2213.31,4195.65 2233.31,4195.65 690.24,4198.51 348.49,4198.9 356.95,4207.83 1017.39,4208.93 1135.31,4210.09 1101.45,4211.06 209.33,4217.29 1925.39,4223.22 1954.65,4226.59 1088.4,4232.48 204.67,4233.39 698.43,4234.52 1193.93,4233.67 2419.06,4241.53 1966.65,4242.59 577.85,4250.7 220.51,4253.48 922.95,4252.83 1087.95,4253.49 1119.95,4255.49 587.65,4262.63 914.25,4262.65 597.09,4273.67 246.4,4276.67 2432.67,4285.99 262.63,4287.49 2389.61,4289.32 670.95,4292.83 1700.95,4293.83 985.76,4305.97 1953.72,4307.54 1074.95,4309.49 2431.41,4311.58 1971.31,4312.09 1026.95,4313.49 2387.05,4315.95 2228.8,4318.06 2245.54,4318.06 2262.89,4318.06 1694.95,4318.83 1962.73,4320.5 177.92,4323.85 2328.31,4327.09 2024.87,4328 2041.12,4327.86 1863.31,4329.09 1988.68,4328.61 2379.73,4328.6 1707.95,4331.83 2241.95,4333.83 315.95,4335.83 2435.49,4336.87 1670.72,4339.15 1065.31,4340.09 1022.95,4341.49 1128.95,4343.83 2305.19,4344.57 2329.81,4344.12 2362.2,4344.57 982.95,4345.49 1002.95,4345.49 618.95,4345.83 960.86,4345.88 195.86,4346.8 1760.31,4348.09 1748.87,4358.42 357.95,4358.83 948.72,4359.25 1817.31,4359.09 379.95,4359.83 1128.95,4359.83 209.63,4361.83 833.31,4365.09 232.18,4366.02 2425.99,4367 297.95,4367.83 1735.27,4367.93 134.94,4369.34 982.95,4369.49 1002.95,4369.49 1054.95,4369.49 97.66,4370.43 961.14,4370.4 2408.84,4379 2028.31,4380.09 1015.62,4381.07 2234.31,4381.09 324.92,4382.12 624.16,4384.37 1974.31,4384.09 233.79,4384.89 2209.64,4386.27 2016.31,4390.09 2035.31,4390.09 1995.31,4391.09 196.04,4392.92 982.95,4393.49 1002.95,4393.49 1026.95,4393.49 1050.95,4393.49 2252.1,4392.72 961.59,4394.69 2426.58,4398.37 296.95,4398.83 2191.63,4400.31 324.88,4404.38 1757.31,4404.09 98.86,4405.77 2208.67,4405.96 2035.31,4410.09 2141.31,4410.09 2051.31,4413.09 216.52,4415.01 359.95,4414.83 2242.74,4415 1009.15,4416.49 1026.95,4417.49 1050.95,4417.49 2090.31,4417.09 624.61,4417.8 987.52,4417.71 2434.68,4418 2258.99,4421.75 110.11,4423.44 324.85,4426.65 1977.31,4427.09 2206.41,4426.63 297.95,4427.83 361.95,4429.83 2188.55,4431.61 811.42,4434.49 2425.4,4437.44 2092.31,4439.09 942.95,4441.49 1026.95,4441.49 1050.95,4441.49 1074.95,4441.49 968.95,4442.02 624.45,4443.53 2241.12,4444.06 2144.31,4446.09 100.07,4447.53 811.49,4447.06 2205.44,4446.64 206.31,4449.09 324.7,4448.84 361.95,4448.83 1671.16,4448.78 2163.31,4454.09 2111.31,4455.09 2260.82,4456.33 811.55,4461.82 2236.31,4462.09 2415.93,4465.26 361.95,4466.83 661.1,4470.3 644.31,4471.09 1094.95,4471.09 2391.07,4477.69 373.08,4481.02 1106.31,4482.09 1979.31,4482.09 1675.07,4483.09 608.28,4488.42 1437.69,4490.38 901.04,4491.25 914.5,4491 623,4502.34 1979.31,4502.09 2311.18,4504.11 2052.31,4506.09 2008.95,4507.99 2031.38,4508 640.46,4509.87 668.82,4510.58 243.02,4510.98 2135.31,4513.09 326.95,4517.83 651.31,4520.09 230.98,4521.42 1979.31,4523.09 978.31,4524.09 715.95,4524.81 2002.31,4526.09 1679.52,4529.29 668.01,4530.47 2241.31,4530.09 2307.96,4529.94 2204.31,4534.09 330.95,4534.83 899.93,4536.52 801.71,4540 1435.63,4540.08 2013.95,4540.49 1680.95,4542.83 991.61,4546.04 2211.95,4545.83 315.95,4546.83 668.31,4547.09 347.95,4549.83 808.56,4551.24 1075.31,4554.99 2023.95,4555.49 2268.57,4554.81 2113.31,4559.09 2203.31,4559.09 373.21,4560.69 2085.31,4561.09 335.95,4561.83 702.99,4563.21 722.33,4562.64 819.2,4562.93 684.99,4567.31 1963.1,4569.28 2242.31,4569.09 773.66,4570.34 947.61,4570.95 1677.23,4572 963.71,4573.09 696.86,4574.05 826.64,4574 2115.31,4575.09 2204.31,4576.09 2085.31,4577.09 1023.49,4578.51 1082.61,4578.77 334.95,4579.83 389.65,4580.56 2102.31,4583.09 1964.4,4587.99 2030.31,4588.09 1122.01,4589.34 2114.31,4589.09 773.82,4590.18 1085.16,4591.49 1003.4,4594.23 2128.31,4594.09 409.52,4598.38 2105.31,4598.09 2204.31,4599.09 2118.31,4602.09 1791.31,4603.09 1964.08,4604.9 990.52,4605.64 832.48,4613.72 846.14,4613.85 865.79,4613.98 882.73,4614.13 899.68,4614.28 916.62,4614.42 933.56,4614.57 950.51,4614.72 1757.31,4620.09 2204.31,4622.09 1963.31,4623.09 1683.58,4628.36 2157.31,4639.09 1683.5,4640.7 2031.31,4642.09 354.88,4643.09 378.78,4643.38 404,4643.28 1103.31,4645.09 1126.3,4647.01 1015.54,4647.95 2128.31,4648.09 2145.31,4648.09 835.07,4648.84 857.23,4648.92 874.85,4649 899.71,4649.01 921.21,4649.06 937.42,4649 952.97,4649 968.22,4649.04 1038.17,4649 1058.82,4648.9 1086.35,4648.64 434.89,4651.77 1942.31,4654.09 1682.43,4660.38 449,4662.52 2198.44,4662.64 1469.22,4665.63 1456.64,4666.89 1999.31,4670.09 2025.31,4670.09 1468.95,4679.49 1456.1,4679.83 2201.76,4681.75 2128.5,4683.37 1962.31,4684.09 2068.31,4686.09 1453.81,4698.15 1983.08,4701.34 1964.31,4702.09 2076.11,4701.93 2200.89,4701.93 1648.95,4704.83 2071.71,4714.98 2202.31,4721.09 1984.31,4723.09 1912.99,4723.69 1645.95,4725.83 513.63,4729.43 1896.31,4729.09 2173.11,4730.55 2199.89,4738.58 1918.31,4739.09 2134.82,4746.15 1668.91,4749.59 1896.31,4751.09 2200.31,4755.09 2119.22,4757.5 1644.95,4759.83 2212.95,4767.83 562.1,4778.61 1684.87,4782.73 1712.74,4783.17 2180.31,4783.09 1740.6,4783.61 1754.73,4784.49 1768.47,4784.05 1796.33,4784.49 1782.28,4784.72 1824.2,4784.93 1852.07,4785.37 1924.31,4785.09 1950.31,4786.09 1698.16,4791.67 1725.18,4792.04 2166.73,4792.83 1808.95,4794.17 1015.95,4794.83 1148.86,4795.5 1189.06,4795.5 1836.31,4795.06 991.95,4795.83 967.95,4796.83 1075.93,4797.17 1265.27,4796.68 1922.31,4797.09 1057.53,4798.37 1101.18,4797.8 1230.42,4797.8 1292.01,4799.46 1314.24,4799.46 732.01,4799.68 1903.95,4799.83 598.34,4812.33 1531.95,4822.83 1726.08,4825.11 1819.31,4825.09 1836.31,4826.09 2115.52,4826.81 2154.15,4830.77 737.95,4833.83 791.15,4833.98 1800.95,4833.83 1713.95,4835.83 1518.95,4838.83 2070.14,4839.89 1017.95,4840.83 1895.95,4840.83 754.95,4842.83 1820.95,4842.83 1731.95,4843.83 837.31,4850.22 2103.03,4849.79 1840.95,4851.83 952.95,4852.83 1711.95,4852.83 1800.95,4853.83 2133.55,4854.15 1894.95,4858.83 1821.95,4859.83 1953.31,4861.09 1035.95,4861.83 1935.32,4861.62 1979.31,4862.09 967.95,4867.83 739.97,4870.16 2071.33,4873.17 1739.95,4873.83 2103.83,4873.96 1402.88,4875.72 1694.95,4875.83 1893.95,4875.83 783.95,4877.83 863.95,4877.83 1788.95,4877.83 1653.92,4878.99 916.95,4880.83 2161.28,4881.49 834.95,4881.83 982.95,4882.83 1053.95,4882.83 1348.37,4885.39 890.95,4885.83 1505.96,4886.99 699.95,4888.83 1823.31,4891.09 843.95,4891.83 928.95,4892.83 1697.31,4893.09 1885.31,4893.09 1721.31,4894.09 1744.31,4894.09 1791.31,4894.09 1632.18,4894.77 2139.09,4896.95 997.95,4897.83 1418.82,4897.74 1506.27,4899.72 2085.99,4902.49 911.95,4903.83 1071.95,4903.83 1211.95,4903.83 2160.49,4907.65 1012.95,4912.83 1231.95,4916.83 697.95,4917.83 2123.24,4919.53 1402.16,4920.72 1177.95,4921.83 1361.38,4922.44 1089.95,4924.83 1885.32,4924.68 638.76,4927.07 907.95,4926.83 2043.59,4927.46 1027.95,4927.83 2005.16,4928.25 1508.95,4930.83 1248.95,4934.83 2080.84,4934.59 2103.95,4940.49 698.95,4941.83 1042.95,4942.83 639.03,4944.32 1985.34,4944.5 1303.79,4945.45 1107.95,4945.83 2125.22,4949.25 1391.25,4954.03 1263.95,4954.83 1348.17,4955.18 1999.21,4955.2 1867.95,4955.83 2036.86,4955.99 829.53,4956.63 1206.95,4956.83 910.95,4958.83 698.95,4960.49 1414.22,4961.5 1885.95,4960.83 1057.95,4961.83 1138.95,4961.83 1971.45,4962.99 851.95,4963.83 785.95,4964.83 1175.95,4965.83 1308.22,4966.48 636.45,4967.99 2136.45,4967.99 736.1,4971.68 1943.87,4972.2 2157.72,4973.43 1512.95,4974.83 2023.95,4975.49 1077.95,4977.83 1280.95,4978.83 800.17,4980.79 1889.95,4980.83 907.95,4984.83 1345.87,4985.63 2148.21,4986.11 1532.95,4987.83 1976.23,4987.69 2003.95,4990.49 1098.95,4993.83 1520.95,4993.83 1943.87,4996.44 1378.61,4997.69 1323.72,4998.59 992.66,4999.7 1892.95,5000.83 912.95,5006.83 1844.31,5008.09 1121.95,5009.83 1775.66,5010.58 2023.95,5010.49 1144.95,5010.83 1167.95,5011.83 2132.75,5012.26 1190.95,5012.83 1402.33,5012.99 1011.48,5014.1 1214.95,5013.83 1885.95,5018.83 1349.19,5026.27 1303.95,5027.83 2038.95,5027.99 2121.45,5027.99 1232.95,5029.83 1040.27,5034.03 1113.35,5037.35 1144.35,5038.45 2101.45,5042.38 2058.95,5042.99 968.3,5047.31 1186.43,5048.42 1253.95,5050.83 1063.52,5056.17 759.64,5058.5 810.5,5061.04 1307.95,5060.83 706.78,5061.85 1503.95,5065.83 1254.95,5072.83 1539.95,5074.83 1961.31,5076.09 1603.95,5078.83 1375.76,5080.53 641.54,5080.99 673.62,5081.23 1699.31,5082.09 1835.94,5082.26 1854.97,5082.34 1878.14,5082.41 1897.9,5082.32 1302.95,5084.83 1080.13,5086.06 1254.95,5092.83 1131.07,5100.46 1383.51,5100.46 1417.84,5101.57 1177.57,5103.78 1350.3,5105.99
